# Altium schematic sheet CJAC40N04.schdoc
size 127 x 101 mm
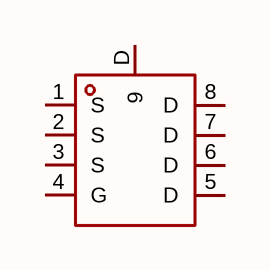
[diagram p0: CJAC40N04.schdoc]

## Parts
Q?  cjac40n04  [PDFNWB-8L_L5.8-W4.9-P1.27-BL-EP]  (value not drawn)

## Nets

Not connected (* = marked no-connect by the designer): Q? 1(S) 2(S) 3(S) 4(G) 5(D) 6(D) 7(D) 8(D) D(9)

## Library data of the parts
Q? = cjac40n04: 数量:1个N沟道;漏源电压(Vdss):40V;连续漏极电流(Id):40A;导通电阻(RDS(on)):9.5mΩ@10V;耗散功率(Pd):4W;阈值电压(Vgs(th)):1V;; Manufacturer: CJ(江苏长电/长晶); AddInBom: yes; ModelId: 1256e5ee62424723ad49ce64008db3ff; ModelTransform: 202.7555,242.1255,0,0,0,0,0,0,0; Number: 1个N沟道; Drain to Source Voltage: 40V; Current - Continuous Drain(Id): 40A; Pd - Power Dissipation: 4W; Gate Threshold Voltage (Vgs(th)): 1V; Gate Charge(Qg): 48nC@10V; Input Capacitance(Ciss): 1.98nF; Reverse Transfer Capacitance (Crss@Vds): 125pF; Type: N沟道; Output Capacitance(Coss): 155pF; Vgs: ±20V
